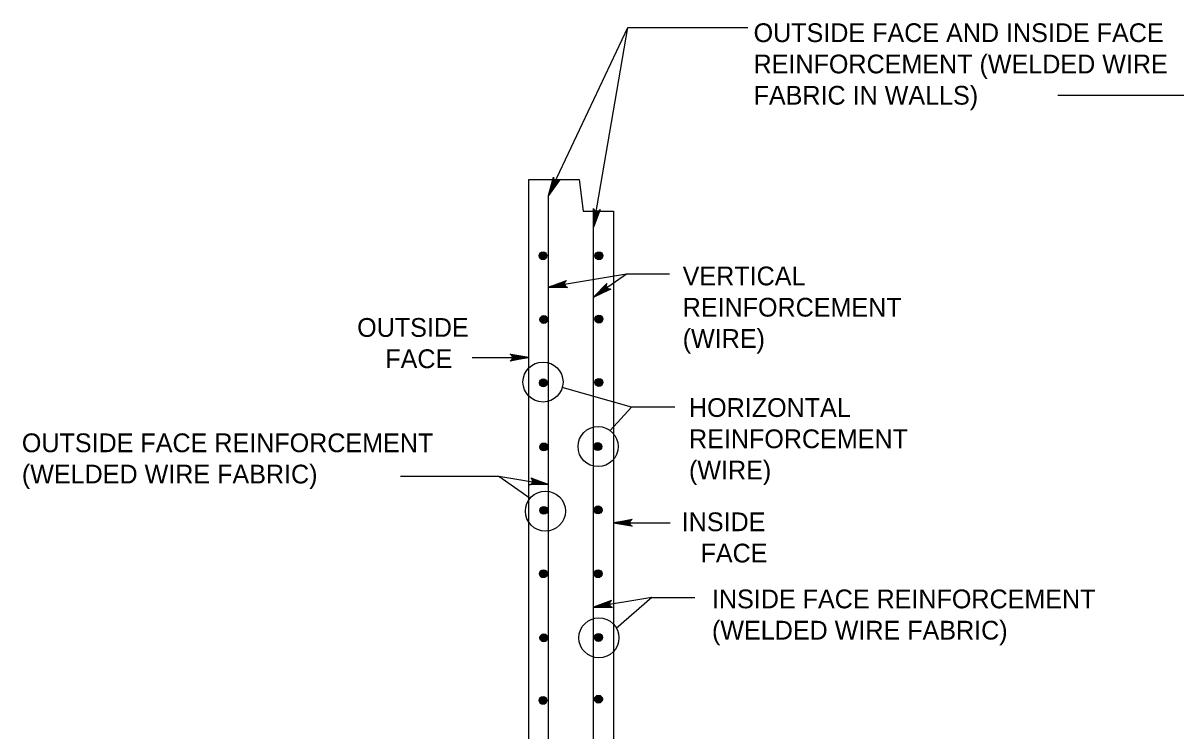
# Model space of a CAD drawing. Extents: x -6420 to 49575, y -4552 to 11624.
# Drawn here: x 8424 to 9028, y 3027 to 3399 of the extents above; entities that cross this region are included whole.
import ezdxf

# ---------------------------------------------------------------- set-up
doc = ezdxf.new("R2010")
doc.units = 0
doc.layers.add('1', color=7, linetype='Continuous')

msp = doc.modelspace()

# ---------------------------------------------------------------- linework, layer by layer
at = {"layer": '1'}
for p, q in [((8688.89, 2783.39), (8688.89, 3316.72)), ((8688.89, 3316.72), (8715.28, 3316.72)), ((8715.28, 3316.72), (8717.36, 3300.06)), ((8699.31, 2797.64), (8699.31, 3308.39)), ((8717.36, 3300.06), (8733.34, 3300.06)), ((8733.34, 3300.06), (8733.34, 2827.84)), ((8722.92, 2805.42), (8722.92, 3291.72)), ((8740.06, 3267.15), (8699.31, 3260.29)), ((8740.06, 3267.15), (8722.92, 3255.03)), ((8762.71, 3267.15), (8740.06, 3267.15)), ((8659.2, 3223.3), (8688.89, 3223.3)), ((8696.37, 3210.49), (8696.37, 3210.49)), ((8742.78, 3197.36), (8706.49, 3207.71)), ((8742.78, 3197.36), (8731.54, 3185.04)), ((8765.43, 3197.36), (8742.78, 3197.36)), ((8725.26, 3176.63), (8725.26, 3176.63)), ((8621.71, 3161.17), (8673.14, 3161.17)), ((8673.14, 3161.17), (8689.59, 3149.53)), ((8673.14, 3161.17), (8699.31, 3156.76)), ((8697.63, 3142.77), (8697.63, 3142.77)), ((8733.34, 3136.66), (8763.03, 3136.66)), ((8753.38, 3097.53), (8722.92, 3092.4)), ((8753.38, 3097.53), (8734.66, 3081.13)), ((8753.38, 3097.53), (8776.03, 3097.53)), ((8725.68, 3076.31), (8725.68, 3076.31))]:
    msp.add_line(p, q, dxfattribs=at)
for points in [[(8699.31, 3308.39), (8740.88, 3396.38), (8803.74, 3396.38)], [(8722.92, 3291.72), (8740.88, 3396.38)], [(9167.38, 3308.39), (9138.24, 3360.78), (8966.38, 3360.78)], [(8699.31, 3308.39), (8701.81, 3317.95), (8701.88, 3317.5), (8701.96, 3317.05), (8702.17, 3316.74), (8702.38, 3316.42), (8702.65, 3316.23), (8702.92, 3316.04), (8703.24, 3315.96), (8703.56, 3315.87), (8703.94, 3315.9), (8704.31, 3315.94), (8704.71, 3316.16), (8705.1, 3316.39), (8699.31, 3308.39), (8704.71, 3316.16), (8704.31, 3315.94), (8699.31, 3308.39), (8703.94, 3315.9), (8703.56, 3315.87), (8699.31, 3308.39), (8703.24, 3315.96), (8702.92, 3316.04), (8699.31, 3308.39), (8702.65, 3316.23), (8702.38, 3316.42), (8699.31, 3308.39), (8702.17, 3316.74), (8701.96, 3317.05), (8699.31, 3308.39), (8701.88, 3317.5)], [(8722.92, 3291.72), (8722.77, 3301.6), (8722.96, 3301.19), (8723.15, 3300.78), (8723.44, 3300.53), (8723.73, 3300.29), (8724.04, 3300.18), (8724.35, 3300.07), (8724.68, 3300.07), (8725.01, 3300.07), (8725.37, 3300.2), (8725.72, 3300.34), (8726.04, 3300.66), (8726.36, 3300.99), (8722.92, 3291.72), (8726.04, 3300.66), (8725.72, 3300.34), (8722.92, 3291.72), (8725.37, 3300.2), (8725.01, 3300.07), (8722.92, 3291.72), (8724.68, 3300.07), (8724.35, 3300.07), (8722.92, 3291.72), (8724.04, 3300.18), (8723.73, 3300.29), (8722.92, 3291.72), (8723.44, 3300.53), (8723.15, 3300.78), (8722.92, 3291.72), (8722.96, 3301.19)], [(8699.31, 3260.29), (8708.65, 3263.72), (8708.32, 3263.4), (8708, 3263.08), (8707.86, 3262.72), (8707.72, 3262.37), (8707.72, 3262.03), (8707.72, 3261.7), (8707.83, 3261.39), (8707.94, 3261.07), (8708.19, 3260.78), (8708.43, 3260.49), (8708.85, 3260.3), (8709.26, 3260.1), (8699.31, 3260.29), (8708.85, 3260.3), (8708.43, 3260.49), (8699.31, 3260.29), (8708.19, 3260.78), (8707.94, 3261.07), (8699.31, 3260.29), (8707.83, 3261.39), (8707.72, 3261.7), (8699.31, 3260.29), (8707.72, 3262.03), (8707.72, 3262.37), (8699.31, 3260.29), (8707.86, 3262.72), (8708, 3263.08), (8699.31, 3260.29), (8708.32, 3263.4)], [(8722.92, 3255.03), (8729.85, 3262.17), (8729.69, 3261.74), (8729.54, 3261.31), (8729.57, 3260.93), (8729.6, 3260.55), (8729.74, 3260.25), (8729.89, 3259.95), (8730.12, 3259.72), (8730.36, 3259.48), (8730.7, 3259.32), (8731.05, 3259.17), (8731.51, 3259.17), (8731.97, 3259.18), (8722.92, 3255.03), (8731.51, 3259.17), (8731.05, 3259.17), (8722.92, 3255.03), (8730.7, 3259.32), (8730.36, 3259.48), (8722.92, 3255.03), (8730.12, 3259.72), (8729.89, 3259.95), (8722.92, 3255.03), (8729.74, 3260.25), (8729.6, 3260.55), (8722.92, 3255.03), (8729.57, 3260.93), (8729.54, 3261.31), (8722.92, 3255.03), (8729.69, 3261.74)], [(8688.89, 3223.3), (8679.11, 3221.47), (8679.48, 3221.73), (8679.86, 3221.99), (8680.05, 3222.32), (8680.25, 3222.64), (8680.3, 3222.97), (8680.36, 3223.3), (8680.3, 3223.63), (8680.25, 3223.96), (8680.05, 3224.29), (8679.86, 3224.61), (8679.48, 3224.87), (8679.11, 3225.14), (8688.89, 3223.3), (8679.48, 3224.87), (8679.86, 3224.61), (8688.89, 3223.3), (8680.05, 3224.29), (8680.25, 3223.96), (8688.89, 3223.3), (8680.3, 3223.63), (8680.36, 3223.3), (8688.89, 3223.3), (8680.3, 3222.97), (8680.25, 3222.64), (8688.89, 3223.3), (8680.05, 3222.32), (8679.86, 3221.99), (8688.89, 3223.3), (8679.48, 3221.73)], [(8699.31, 3156.76), (8689.35, 3156.58), (8689.77, 3156.77), (8690.18, 3156.97), (8690.43, 3157.26), (8690.68, 3157.55), (8690.79, 3157.86), (8690.9, 3158.18), (8690.89, 3158.51), (8690.89, 3158.84), (8690.76, 3159.2), (8690.62, 3159.55), (8690.29, 3159.87), (8689.96, 3160.19), (8699.31, 3156.76), (8690.29, 3159.87), (8690.62, 3159.55), (8699.31, 3156.76), (8690.76, 3159.2), (8690.89, 3158.84), (8699.31, 3156.76), (8690.89, 3158.51), (8690.9, 3158.18), (8699.31, 3156.76), (8690.79, 3157.86), (8690.68, 3157.55), (8699.31, 3156.76), (8690.43, 3157.26), (8690.18, 3156.97), (8699.31, 3156.76), (8689.77, 3156.77)], [(8733.34, 3136.66), (8743.12, 3138.49), (8742.75, 3138.23), (8742.37, 3137.97), (8742.18, 3137.64), (8741.98, 3137.31), (8741.92, 3136.99), (8741.87, 3136.66), (8741.92, 3136.33), (8741.98, 3136), (8742.18, 3135.67), (8742.37, 3135.35), (8742.75, 3135.08), (8743.12, 3134.82), (8733.34, 3136.66), (8742.75, 3135.08), (8742.37, 3135.35), (8733.34, 3136.66), (8742.18, 3135.67), (8741.98, 3136), (8733.34, 3136.66), (8741.92, 3136.33), (8741.87, 3136.66), (8733.34, 3136.66), (8741.92, 3136.99), (8741.98, 3137.31), (8733.34, 3136.66), (8742.18, 3137.64), (8742.37, 3137.97), (8733.34, 3136.66), (8742.75, 3138.23)], [(8722.92, 3092.4), (8732.88, 3092.22), (8732.46, 3092.41), (8732.05, 3092.61), (8731.8, 3092.9), (8731.55, 3093.19), (8731.44, 3093.51), (8731.33, 3093.82), (8731.33, 3094.15), (8731.34, 3094.49), (8731.47, 3094.84), (8731.61, 3095.2), (8731.94, 3095.52), (8732.27, 3095.84), (8722.92, 3092.4), (8731.94, 3095.52), (8731.61, 3095.2), (8722.92, 3092.4), (8731.47, 3094.84), (8731.34, 3094.49), (8722.92, 3092.4), (8731.33, 3094.15), (8731.33, 3093.82), (8722.92, 3092.4), (8731.44, 3093.51), (8731.55, 3093.19), (8722.92, 3092.4), (8731.8, 3092.9), (8732.05, 3092.61), (8722.92, 3092.4), (8732.46, 3092.41)]]:
    msp.add_lwpolyline(points, dxfattribs=at)
for centre, radius in [((8696.37, 3276.74), 2.08), ((8696.37, 3276.74), 1.94), ((8696.37, 3276.74), 1.79), ((8696.37, 3276.74), 1.64), ((8696.37, 3276.74), 1.49), ((8696.37, 3276.74), 1.34), ((8696.37, 3276.74), 1.2), ((8696.37, 3276.74), 1.05), ((8696.37, 3276.74), 0.9), ((8696.37, 3276.74), 0.752), ((8696.37, 3276.74), 0.604), ((8696.37, 3276.74), 0.456), ((8696.37, 3276.74), 0.308), ((8696.37, 3276.74), 0.16), ((8725.68, 3276.74), 2.08), ((8725.68, 3276.74), 1.94), ((8725.68, 3276.74), 1.79), ((8725.68, 3276.74), 1.64), ((8725.68, 3276.74), 1.49), ((8725.68, 3276.74), 1.34), ((8725.68, 3276.74), 1.2), ((8725.68, 3276.74), 1.05), ((8725.68, 3276.74), 0.9), ((8725.68, 3276.74), 0.752), ((8725.68, 3276.74), 0.604), ((8725.68, 3276.74), 0.456), ((8725.68, 3276.74), 0.308), ((8725.68, 3276.74), 0.16), ((8696.79, 3243.3), 2.08), ((8696.79, 3243.3), 1.94), ((8696.79, 3243.3), 1.79), ((8696.79, 3243.3), 1.64), ((8696.79, 3243.3), 1.49), ((8696.79, 3243.3), 1.34), ((8696.79, 3243.3), 1.2), ((8696.79, 3243.3), 1.05), ((8696.79, 3243.3), 0.9), ((8696.79, 3243.3), 0.752), ((8696.79, 3243.3), 0.604), ((8696.79, 3243.3), 0.456), ((8696.79, 3243.3), 0.308), ((8696.79, 3243.3), 0.16), ((8725.68, 3243.51), 2.08), ((8725.68, 3243.51), 1.94), ((8725.68, 3243.51), 1.79), ((8725.68, 3243.51), 1.64), ((8725.68, 3243.51), 1.49), ((8725.68, 3243.51), 1.34), ((8725.68, 3243.51), 1.2), ((8725.68, 3243.51), 1.05), ((8725.68, 3243.51), 0.9), ((8725.68, 3243.51), 0.752), ((8725.68, 3243.51), 0.604), ((8725.68, 3243.51), 0.456), ((8725.68, 3243.51), 0.308), ((8725.68, 3243.51), 0.16), ((8696.37, 3210.49), 10.5), ((8696.58, 3210.07), 2.08), ((8696.58, 3210.07), 1.94), ((8696.58, 3210.07), 1.79), ((8696.58, 3210.07), 1.64), ((8696.58, 3210.07), 1.49), ((8696.58, 3210.07), 1.34), ((8696.58, 3210.07), 1.2), ((8696.58, 3210.07), 1.05), ((8696.58, 3210.07), 0.9), ((8696.58, 3210.07), 0.752), ((8696.58, 3210.07), 0.604), ((8696.58, 3210.07), 0.456), ((8696.58, 3210.07), 0.308), ((8696.58, 3210.07), 0.16), ((8725.68, 3210.28), 2.08), ((8725.68, 3210.28), 1.94), ((8725.68, 3210.28), 1.79), ((8725.68, 3210.28), 1.64), ((8725.68, 3210.28), 1.49), ((8725.68, 3210.28), 1.34), ((8725.68, 3210.28), 1.2), ((8725.68, 3210.28), 1.05), ((8725.68, 3210.28), 0.9), ((8725.68, 3210.28), 0.752), ((8725.68, 3210.28), 0.604), ((8725.68, 3210.28), 0.456), ((8725.68, 3210.28), 0.308), ((8725.68, 3210.28), 0.16), ((8725.26, 3176.63), 10.5), ((8696.79, 3176.42), 2.08), ((8696.79, 3176.42), 1.94), ((8696.79, 3176.42), 1.79), ((8696.79, 3176.42), 1.64), ((8696.79, 3176.42), 1.49), ((8696.79, 3176.42), 1.34), ((8696.79, 3176.42), 1.2), ((8696.79, 3176.42), 1.05), ((8696.79, 3176.42), 0.9), ((8696.79, 3176.42), 0.752), ((8696.79, 3176.42), 0.604), ((8696.79, 3176.42), 0.456), ((8696.79, 3176.42), 0.308), ((8696.79, 3176.42), 0.16), ((8725.05, 3176.63), 2.08), ((8725.05, 3176.63), 1.94), ((8725.05, 3176.63), 1.79), ((8725.05, 3176.63), 1.64), ((8725.05, 3176.63), 1.49), ((8725.05, 3176.63), 1.34), ((8725.05, 3176.63), 1.2), ((8725.05, 3176.63), 1.05), ((8725.05, 3176.63), 0.9), ((8725.05, 3176.63), 0.752), ((8725.05, 3176.63), 0.604), ((8725.05, 3176.63), 0.456), ((8725.05, 3176.63), 0.308), ((8725.05, 3176.63), 0.16), ((8697.63, 3142.77), 10.5), ((8696.79, 3143.19), 2.08), ((8696.79, 3143.19), 1.94), ((8696.79, 3143.19), 1.79), ((8696.79, 3143.19), 1.64), ((8696.79, 3143.19), 1.49), ((8696.79, 3143.19), 1.34), ((8696.79, 3143.19), 1.2), ((8696.79, 3143.19), 1.05), ((8696.79, 3143.19), 0.9), ((8696.79, 3143.19), 0.752), ((8696.79, 3143.19), 0.604), ((8696.79, 3143.19), 0.456), ((8696.79, 3143.19), 0.308), ((8696.79, 3143.19), 0.16), ((8725.26, 3143.4), 2.08), ((8725.26, 3143.4), 1.94), ((8725.26, 3143.4), 1.79), ((8725.26, 3143.4), 1.64), ((8725.26, 3143.4), 1.49), ((8725.26, 3143.4), 1.34), ((8725.26, 3143.4), 1.2), ((8725.26, 3143.4), 1.05), ((8725.26, 3143.4), 0.9), ((8725.26, 3143.4), 0.752), ((8725.26, 3143.4), 0.604), ((8725.26, 3143.4), 0.456), ((8725.26, 3143.4), 0.308), ((8725.26, 3143.4), 0.16), ((8696.58, 3109.96), 2.08), ((8696.58, 3109.96), 1.94), ((8696.58, 3109.96), 1.79), ((8696.58, 3109.96), 1.64), ((8696.58, 3109.96), 1.49), ((8696.58, 3109.96), 1.34), ((8696.58, 3109.96), 1.2), ((8696.58, 3109.96), 1.05), ((8696.58, 3109.96), 0.9), ((8696.58, 3109.96), 0.752), ((8696.58, 3109.96), 0.604), ((8696.58, 3109.96), 0.456), ((8696.58, 3109.96), 0.308), ((8696.58, 3109.96), 0.16), ((8725.26, 3109.96), 2.08), ((8725.26, 3109.96), 1.94), ((8725.26, 3109.96), 1.79), ((8725.26, 3109.96), 1.64), ((8725.26, 3109.96), 1.49), ((8725.26, 3109.96), 1.34), ((8725.26, 3109.96), 1.2), ((8725.26, 3109.96), 1.05), ((8725.26, 3109.96), 0.9), ((8725.26, 3109.96), 0.752), ((8725.26, 3109.96), 0.604), ((8725.26, 3109.96), 0.456), ((8725.26, 3109.96), 0.308), ((8725.26, 3109.96), 0.16), ((8725.68, 3076.31), 10.5), ((8696.79, 3076.31), 2.08), ((8696.79, 3076.31), 1.94), ((8696.79, 3076.31), 1.79), ((8696.79, 3076.31), 1.64), ((8696.79, 3076.31), 1.49), ((8696.79, 3076.31), 1.34), ((8696.79, 3076.31), 1.2), ((8696.79, 3076.31), 1.05), ((8696.79, 3076.31), 0.9), ((8696.79, 3076.31), 0.752), ((8696.79, 3076.31), 0.604), ((8696.79, 3076.31), 0.456), ((8725.47, 3076.52), 2.08), ((8725.47, 3076.52), 1.94), ((8725.47, 3076.52), 1.79), ((8725.47, 3076.52), 1.64), ((8725.47, 3076.52), 1.49), ((8725.47, 3076.52), 1.34), ((8725.47, 3076.52), 1.2), ((8725.47, 3076.52), 1.05), ((8725.47, 3076.52), 0.9), ((8725.47, 3076.52), 0.752), ((8725.47, 3076.52), 0.604), ((8725.47, 3076.52), 0.456), ((8725.47, 3076.52), 0.308), ((8696.79, 3076.31), 0.308), ((8696.79, 3076.31), 0.16), ((8725.47, 3076.52), 0.16), ((8696.37, 3043.51), 2.08), ((8696.37, 3043.51), 1.94), ((8696.37, 3043.51), 1.79), ((8696.37, 3043.51), 1.64), ((8696.37, 3043.51), 1.49), ((8696.37, 3043.51), 1.34), ((8696.37, 3043.51), 1.2), ((8696.37, 3043.51), 1.05), ((8696.37, 3043.51), 0.9), ((8696.37, 3043.51), 0.752), ((8696.37, 3043.51), 0.604), ((8696.37, 3043.51), 0.456), ((8696.37, 3043.51), 0.308), ((8696.37, 3043.51), 0.16), ((8725.47, 3044.14), 2.08), ((8725.47, 3044.14), 1.94), ((8725.47, 3044.14), 1.79), ((8725.47, 3044.14), 1.64), ((8725.47, 3044.14), 1.49), ((8725.47, 3044.14), 1.34), ((8725.47, 3044.14), 1.2), ((8725.47, 3044.14), 1.05), ((8725.47, 3044.14), 0.9), ((8725.47, 3044.14), 0.752), ((8725.47, 3044.14), 0.604), ((8725.47, 3044.14), 0.456), ((8725.47, 3044.14), 0.308), ((8725.47, 3044.14), 0.16)]:
    msp.add_circle(centre, radius, dxfattribs=at)

# ---------------------------------------------------------------- texts
for s, height, p in [('OUTSIDE FACE AND INSIDE FACE', 9.8425, (8806.78, 3388.81)), ('REINFORCEMENT (WELDED WIRE', 9.8425, (8806.78, 3372.4)), ('FABRIC IN WALLS)', 9.8425, (8806.78, 3356)), ('VERTICAL', 9.843, (8769.6, 3261.22)), ('REINFORCEMENT', 9.8425, (8769.6, 3244.81)), ('OUTSIDE', 9.843, (8598.93, 3234.2)), ('(WIRE)', 9.843, (8769.6, 3228.41)), ('FACE', 9.843, (8613.69, 3217.79)), ('HORIZONTAL', 9.843, (8772.91, 3192.19)), ('REINFORCEMENT', 9.8425, (8772.91, 3175.79)), ('OUTSIDE FACE REINFORCEMENT', 9.8425, (8423.13, 3173.69)), ('(WELDED WIRE FABRIC)', 9.8425, (8423.13, 3157.29)), ('(WIRE)', 9.843, (8772.91, 3159.38)), ('INSIDE', 9.843, (8769.11, 3132.25)), ('FACE', 9.843, (8778.96, 3115.85)), ('INSIDE FACE REINFORCEMENT', 9.8425, (8784.96, 3091.8)), ('(WELDED WIRE FABRIC)', 9.8425, (8784.96, 3075.4))]:
    msp.add_text(s, height=height, dxfattribs=at).set_placement(p)

doc.saveas('drawing.dxf')
